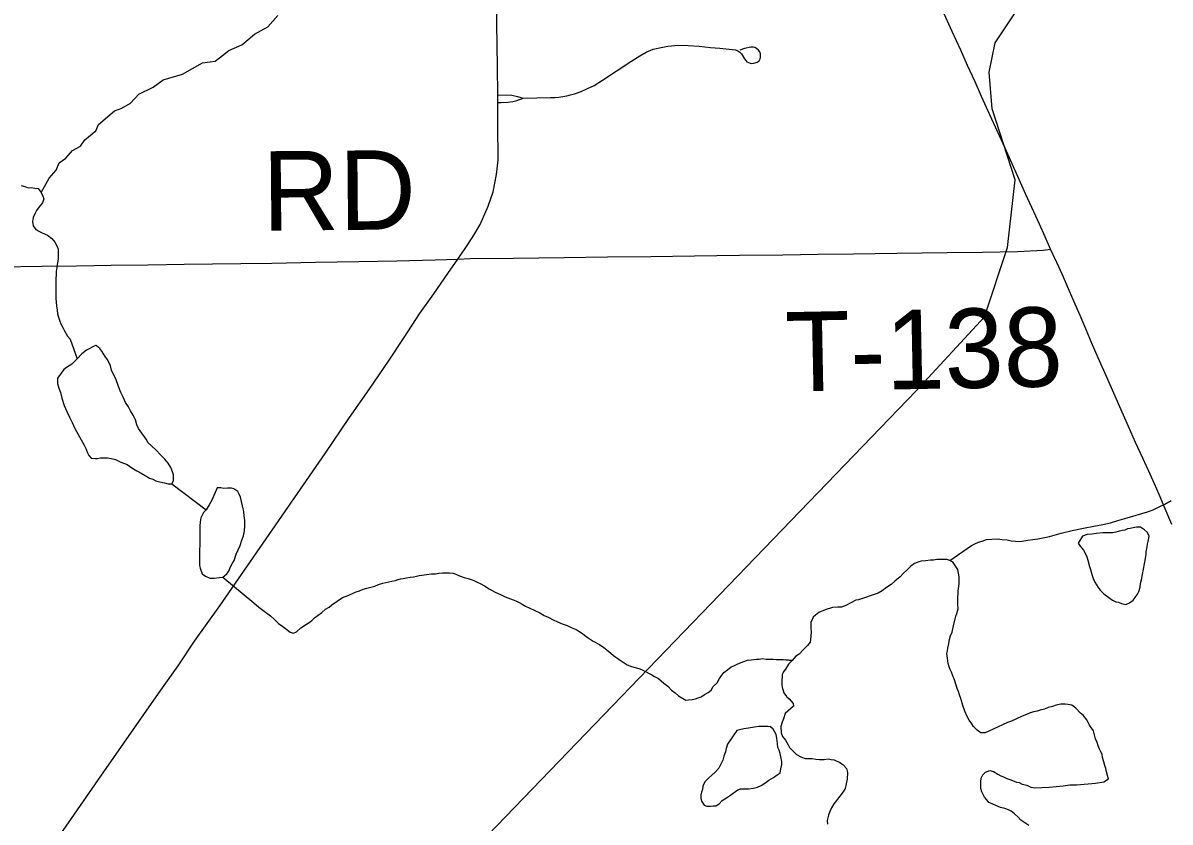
# Model space of a CAD drawing. Extents: x 103424 to 290657, y 38711 to 110967.
# Drawn here: x 167708 to 172070, y 45205 to 48243 of the extents above; entities that cross this region are included whole.
import ezdxf

# ---------------------------------------------------------------- set-up
doc = ezdxf.new("R2010")
doc.units = 0
for name, color, linetype in [('GM_X_County_Road', 7, 'Continuous'), ('GM_X_Minor_Lake', 7, 'Continuous'), ('GM_X_Minor_River', 7, 'Continuous'), ('GM_X_Rail_Line', 7, 'Continuous'), ('GM_X_State_Route', 7, 'Continuous'), ('GM_X_Township_Road', 7, 'Continuous'), ('GM_X_Township_Road_Text', 7, 'Continuous')]:
    doc.layers.add(name, color=color, linetype=linetype)

msp = doc.modelspace()

# ---------------------------------------------------------------- linework, layer by layer
at = {"layer": 'GM_X_County_Road'}
msp.add_lwpolyline([(167838.1, 45140.8), (167926.6, 45268.8), (168015.1, 45396.8), (168091.4, 45505.3), (168167.7, 45613.9), (168232.8, 45706.4), (168298, 45799), (168360.2, 45892.5), (168408.5, 45959.8), (168456.8, 46027.1), (168550.6, 46162.9), (168644.4, 46298.7), (168703.8, 46384.7), (168763.2, 46470.8), (168856.8, 46606.8), (168950.3, 46742.8), (169024, 46850), (169097.7, 46957.1), (169156.9, 47047), (169216.2, 47136.8), (169269.8, 47213.8), (169323.5, 47290.9), (169361.7, 47344.7), (169389, 47385.5), (169418.7, 47429.8), (169446.4, 47476.7), (169477.5, 47545.9), (169496.2, 47601), (169508.2, 47667.3), (169514.6, 47721.2), (169514, 47856.4), (169513.7, 47940), (169513.4, 47969.6), (169512.2, 48075.7), (169510.3, 48240.8), (169509.3, 48332)], dxfattribs=at)
at = {"layer": 'GM_X_Minor_Lake'}
for points in [[(167984, 47017.3), (167949.9, 46998.8), (167931.8, 46984.6), (167913.8, 46966.3), (167893.8, 46945.9), (167873.8, 46933.7), (167863.7, 46925.5), (167853.8, 46911.3), (167839.8, 46893.1), (167839.9, 46872.9), (167844.1, 46854.8), (167850.3, 46838.7), (167856.5, 46816.5), (167864.8, 46788.3), (167875.1, 46766.2), (167885.3, 46744.1), (167895.5, 46724), (167905.8, 46701.8), (167940.6, 46637.5), (167946.7, 46625.4), (167952.9, 46609.3), (167959, 46599.3), (167967.2, 46589.2), (167981.3, 46587.3), (167991.4, 46587.4), (168003.4, 46589.5), (168015.5, 46589.6), (168029.7, 46589.7), (168043.8, 46587.8), (168059.9, 46583.9), (168080.2, 46573.9), (168104.5, 46564), (168122.7, 46552), (168140.9, 46540.1), (168157.1, 46532.1), (168173.4, 46522.1), (168189.6, 46512.2), (168201.7, 46508.2), (168213.8, 46502.2)], [(167984, 47017.3), (167949.9, 46998.8), (167931.8, 46984.6), (167913.8, 46966.3), (167893.8, 46945.9), (167873.8, 46933.7), (167863.7, 46925.5), (167853.8, 46911.3), (167839.8, 46893.1), (167839.9, 46872.9), (167844.1, 46854.8), (167850.3, 46838.7), (167856.5, 46816.5), (167864.8, 46788.3), (167875.1, 46766.2), (167885.3, 46744.1), (167895.5, 46724), (167905.8, 46701.8), (167940.6, 46637.5), (167946.7, 46625.4), (167952.9, 46609.3), (167959, 46599.3), (167967.2, 46589.2), (167981.3, 46587.3), (167991.4, 46587.4), (168003.4, 46589.5), (168015.5, 46589.6), (168029.7, 46589.7), (168043.8, 46587.8), (168059.9, 46583.9), (168080.2, 46573.9), (168104.5, 46564), (168122.7, 46552), (168140.9, 46540.1), (168157.1, 46532.1), (168173.4, 46522.1), (168189.6, 46512.2), (168201.7, 46508.2), (168213.8, 46502.2), (168228, 46498.3), (168246.2, 46494.4), (168260.3, 46490.5), (168274.4, 46490.6), (168280.4, 46502.7), (168280.3, 46514.8), (168280.2, 46524.9), (168276.1, 46537), (168269.9, 46553.1), (168259.7, 46569.2), (168247.5, 46585.2), (168231.2, 46601.3), (168214.9, 46619.3), (168196.7, 46635.3), (168184.5, 46647.3), (168176.3, 46661.4), (168147.8, 46701.6), (168141.6, 46715.7), (168135.4, 46733.8), (168127.2, 46751.9), (168117, 46768), (168108.8, 46784), (168098.6, 46800.1), (168090.4, 46818.2), (168080.2, 46838.3), (168071.9, 46860.5), (168061.6, 46890.7), (168051.4, 46908.8), (168045.2, 46922.8), (168041.1, 46939), (168034.9, 46953), (168028.8, 46965.1), (168020.6, 46975.1), (168014.5, 46985.2), (168008.4, 46995.2), (168000.2, 47005.3), (167988.1, 47015.3), (167986, 47017.3), (167984, 47017.3)], [(168213.8, 46502.2), (168228, 46498.3), (168246.2, 46494.4), (168260.3, 46490.5), (168274.4, 46490.6), (168280.4, 46502.7), (168280.3, 46514.8), (168280.2, 46524.9), (168276.1, 46537), (168269.9, 46553.1), (168259.7, 46569.2), (168247.5, 46585.2), (168231.2, 46601.3), (168214.9, 46619.3), (168196.7, 46635.3), (168184.5, 46647.3), (168176.3, 46661.4), (168147.8, 46701.6), (168141.6, 46715.7), (168135.4, 46733.8), (168127.2, 46751.9), (168117, 46768), (168108.8, 46784), (168098.6, 46800.1), (168090.4, 46818.2), (168080.2, 46838.3), (168071.9, 46860.5), (168061.6, 46890.7), (168051.4, 46908.8), (168045.2, 46922.8), (168041.1, 46939), (168034.9, 46953), (168028.8, 46965.1), (168020.6, 46975.1), (168014.5, 46985.2), (168008.4, 46995.2), (168000.2, 47005.3), (167988.1, 47015.3), (167986, 47017.3), (167984, 47017.3)], [(168445.9, 46475.7), (168426.1, 46429.1), (168416.2, 46410.9), (168404.2, 46392.6), (168394.2, 46382.5), (168384.3, 46362.2), (168382.4, 46346), (168380.5, 46329.9), (168380.6, 46311.7), (168380.8, 46293.6), (168380.9, 46279.4), (168381, 46267.3), (168381.1, 46255.2), (168379.2, 46243.1), (168379.3, 46222.9), (168379.4, 46210.8), (168379.5, 46196.7), (168379.6, 46180.5), (168381.7, 46170.4), (168390, 46148.3), (168402.1, 46140.3), (168418.3, 46132.4), (168434.5, 46132.5), (168454.6, 46134.6), (168468.7, 46136.8), (168482.7, 46149), (168490.7, 46159.1), (168496.6, 46175.3), (168504.6, 46189.5), (168510.6, 46199.6), (168518.4, 46223.9), (168526.4, 46240.1), (168534.3, 46256.3), (168540.2, 46276.6), (168546.1, 46292.8), (168550, 46313), (168551.9, 46331.1), (168551.7, 46351.3), (168549.6, 46369.5), (168547.4, 46385.6), (168545.3, 46395.7), (168543.2, 46407.8), (168539.1, 46423.9), (168534.9, 46440), (168530.8, 46452.1), (168524.7, 46462.1), (168510.5, 46472.1), (168500.4, 46474.1), (168486.3, 46474), (168472.2, 46473.9), (168460, 46475.8), (168449.9, 46475.7), (168445.9, 46475.7)], [(168445.9, 46475.7), (168426.1, 46429.1), (168416.2, 46410.9), (168404.2, 46392.6), (168394.2, 46382.5), (168384.3, 46362.2), (168382.4, 46346), (168380.5, 46329.9), (168380.6, 46311.7), (168380.8, 46293.6), (168380.9, 46279.4), (168381, 46267.3), (168381.1, 46255.2), (168379.2, 46243.1), (168379.3, 46222.9), (168379.4, 46210.8), (168379.5, 46196.7), (168379.6, 46180.5), (168381.7, 46170.4), (168390, 46148.3), (168402.1, 46140.3), (168418.3, 46132.4), (168434.5, 46132.5), (168454.6, 46134.6), (168468.7, 46136.8), (168482.7, 46149), (168490.7, 46159.1)], [(168490.7, 46159.1), (168496.6, 46175.3), (168504.6, 46189.5), (168510.6, 46199.6), (168518.4, 46223.9), (168526.4, 46240.1), (168534.3, 46256.3), (168540.2, 46276.6), (168546.1, 46292.8), (168550, 46313), (168551.9, 46331.1), (168551.7, 46351.3), (168549.6, 46369.5), (168547.4, 46385.6), (168545.3, 46395.7), (168543.2, 46407.8), (168539.1, 46423.9), (168534.9, 46440), (168530.8, 46452.1), (168524.7, 46462.1), (168510.5, 46472.1), (168500.4, 46474.1), (168486.3, 46474), (168472.2, 46473.9), (168460, 46475.8), (168449.9, 46475.7), (168445.9, 46475.7)], [(171976.3, 46206.8), (171976.7, 46208.9), (171978.6, 46221), (171978.5, 46233.1), (171982.4, 46251.3), (171984.3, 46261.4), (171986.3, 46271.5), (171990.1, 46291.8), (171984, 46305.8), (171971.8, 46315.8), (171957.6, 46325.8), (171941.5, 46325.7), (171929.4, 46323.6), (171917.3, 46321.5), (171907.3, 46319.4), (171897.2, 46315.3), (171887.1, 46313.2), (171877.1, 46311.1), (171863, 46307), (171850.9, 46304.9), (171834.8, 46304.7), (171814.6, 46304.6), (171790.4, 46302.4), (171772.3, 46300.3), (171754.2, 46298.1), (171736.1, 46291.9), (171720.4, 46265.9)], [(171720.4, 46265.9), (171728.3, 46253.5), (171740.5, 46239.5), (171746.7, 46227.4), (171752.8, 46213.3), (171756.9, 46201.2), (171763.2, 46177.1), (171767.3, 46165), (171773.5, 46142.8), (171777.6, 46130.7), (171783.8, 46116.7), (171796.1, 46096.6), (171804.2, 46086.5), (171818.4, 46072.5), (171836.7, 46058.5), (171850.9, 46048.5), (171863, 46042.6), (171873.1, 46040.6), (171885.2, 46036.7), (171901.4, 46032.8), (171915.5, 46038.9), (171929.5, 46049.1), (171937.5, 46059.3), (171945.5, 46071.4), (171951.4, 46081.6), (171955.3, 46097.7), (171957.3, 46111.9), (171961.2, 46126), (171976.3, 46206.8)], [(171786.4, 45521.2), (171782.2, 45537.4), (171778.1, 45551.5), (171771.9, 45561.5), (171763.8, 45573.6), (171753.5, 45593.7), (171739.3, 45611.7), (171729.2, 45619.7), (171710.9, 45637.8), (171696.7, 45649.8), (171680.5, 45651.7), (171670.4, 45653.6), (171654.3, 45653.5), (171636.2, 45649.3), (171622.1, 45645.2), (171606, 45641), (171591.9, 45634.9), (171575.8, 45630.7), (171563.8, 45626.6), (171551.7, 45624.5), (171537.6, 45620.3), (171523.5, 45614.2), (171507.5, 45608), (171485.3, 45597.8), (171467.3, 45589.5), (171451.2, 45583.4), (171396.9, 45558.8), (171380.8, 45550.6), (171366.8, 45544.4), (171350.7, 45544.3), (171336.5, 45554.3), (171322.2, 45568.3), (171316.1, 45578.3), (171305.9, 45592.4), (171297.8, 45606.5), (171289.5, 45626.6), (171281.3, 45648.7), (171275.1, 45670.9), (171268.9, 45689), (171264.8, 45701.1), (171260.6, 45713.2), (171254.5, 45729.3), (171250.3, 45745.4), (171244.1, 45761.5), (171238, 45775.6), (171233.9, 45785.7), (171229.8, 45795.7), (171225.6, 45807.8), (171223.5, 45828), (171221.3, 45846.1), (171223.2, 45856.2), (171225.2, 45866.3), (171227.1, 45878.4), (171231, 45898.7), (171234.9, 45912.8), (171240.8, 45927), (171246.7, 45951.2), (171252.6, 45977.5), (171254.5, 45987.6), (171258.4, 45997.8), (171264.3, 46016), (171262.2, 46034.1), (171262.1, 46050.3), (171263.8, 46084.6), (171267.7, 46110.9), (171267.5, 46137.1), (171265.3, 46151.2), (171263.2, 46165.3), (171255, 46177.4), (171244.9, 46191.4), (171232.7, 46199.4), (171220.6, 46203.4), (171206.4, 46203.3), (171194.4, 46203.2), (171182.3, 46203.1), (171170.2, 46201), (171158.1, 46200.9), (171139.9, 46198.7), (171123.8, 46196.6), (171113.8, 46194.5), (171097.7, 46188.3), (171083.6, 46178.1), (171067.6, 46161.9), (171055.6, 46151.7), (171043.6, 46137.5), (171023.6, 46121.2), (171009.6, 46109), (170991.5, 46096.7), (170975.5, 46084.5), (170960.3, 46074.9)], [(170960.3, 46074.9), (170885, 46049.5), (170885, 46049.5), (170874.9, 46049.4), (170836.8, 46029), (170820.7, 46022.8), (170806.6, 46022.7), (170786.4, 46020.5), (170758.3, 46012.3), (170734.1, 46002), (170722.1, 45991.8), (170712.1, 45983.7), (170704.2, 45963.4), (170704.3, 45945.3), (170704.5, 45927.1), (170702.7, 45898.8), (170700.7, 45888.7), (170690.8, 45876.5), (170674.7, 45860.3), (170658.8, 45844), (170646.7, 45835.8), (170632.7, 45819.6), (170618.7, 45805.4), (170606.8, 45787.1), (170598.8, 45774.9), (170594.8, 45764.8), (170593, 45738.6), (170593.1, 45728.5), (170595.2, 45718.4), (170601.4, 45696.2), (170611.6, 45682.2), (170621.7, 45674.2), (170636, 45656.1), (170638.1, 45646), (170606, 45617.6), (170600.1, 45597.3), (170594.2, 45585.2), (170590.3, 45569), (170590.5, 45544.8), (170596.6, 45530.7), (170606.8, 45516.6), (170617, 45498.5), (170623.2, 45488.5), (170635.4, 45476.5), (170649.6, 45462.4), (170667.8, 45452.5), (170682, 45446.5), (170696.1, 45446.7), (170708.2, 45446.7), (170722.3, 45444.8), (170736.4, 45442.9), (170754.6, 45443), (170770.7, 45445.2), (170780.8, 45443.2), (170792.9, 45441.3), (170803, 45437.3), (170813.1, 45433.4), (170827.3, 45423.4), (170839.5, 45409.3), (170843.7, 45393.2), (170841.9, 45369), (170838, 45350.8), (170834.1, 45332.6), (170826.1, 45320.4), (170814.1, 45304.2), (170800.2, 45285.9), (170790.2, 45271.7), (170782.2, 45259.6), (170776.3, 45245.4), (170770.3, 45231.2), (170766.4, 45211), (170766.6, 45196.9)], [(170423, 45553.6), (170387.2, 45500.9), (170381.2, 45484.7), (170379.3, 45472.6), (170373.4, 45456.4), (170369.5, 45440.2), (170361.5, 45426), (170353.6, 45409.8), (170339.6, 45395.6), (170327.6, 45383.4), (170315.6, 45373.2), (170301.5, 45359), (170293.6, 45342.8), (170291.7, 45328.6), (170287.7, 45318.5), (170285.8, 45308.4), (170285.9, 45296.3), (170288, 45284.2), (170298.2, 45270.1), (170308.3, 45266.2), (170322.4, 45266.3), (170332.5, 45266.4), (170342.6, 45266.4), (170354.6, 45274.6), (170366.6, 45286.8), (170382.7, 45297), (170398.7, 45307.2), (170408.8, 45315.4), (170426.8, 45327.6), (170436.8, 45331.7), (170448.9, 45331.8), (170467.1, 45331.9), (170485.2, 45334.1), (170501.3, 45338.2), (170515.4, 45344.4), (170529.4, 45352.6), (170543.5, 45364.8), (170561.5, 45375), (170575.6, 45385.2), (170587.6, 45391.3), (170589.5, 45407.5), (170593.4, 45423.7), (170593.3, 45435.8), (170589.2, 45453.9), (170587, 45466), (170582.9, 45478.1), (170578.8, 45488.2), (170576.7, 45504.3), (170574.5, 45524.5), (170572.4, 45538.6), (170560.1, 45558.7), (170550, 45566.7), (170539.9, 45568.6), (170505.6, 45568.4), (170489.5, 45566.2), (170467.3, 45562), (170449.2, 45559.9), (170433.1, 45555.7), (170423, 45553.6)], [(170423, 45553.6), (170387.2, 45500.9), (170381.2, 45484.7), (170379.3, 45472.6), (170373.4, 45456.4), (170369.5, 45440.2), (170361.5, 45426), (170353.6, 45409.8), (170339.6, 45395.6), (170327.6, 45383.4), (170315.6, 45373.2), (170301.5, 45359), (170293.6, 45342.8), (170291.7, 45328.6), (170287.7, 45318.5), (170285.8, 45308.4), (170285.9, 45296.3), (170288, 45284.2), (170298.2, 45270.1), (170308.3, 45266.2), (170322.4, 45266.3), (170332.5, 45266.4), (170342.6, 45266.4), (170354.6, 45274.6), (170366.6, 45286.8), (170382.7, 45297), (170398.7, 45307.2), (170408.8, 45315.4), (170426.8, 45327.6), (170436.8, 45331.7)], [(170436.8, 45331.7), (170448.9, 45331.8), (170467.1, 45331.9), (170485.2, 45334.1), (170501.3, 45338.2), (170515.4, 45344.4), (170529.4, 45352.6), (170543.5, 45364.8), (170561.5, 45375), (170575.6, 45385.2), (170587.6, 45391.3), (170589.5, 45407.5), (170593.4, 45423.7), (170593.3, 45435.8), (170589.2, 45453.9), (170587, 45466), (170582.9, 45478.1), (170578.8, 45488.2), (170576.7, 45504.3), (170574.5, 45524.5), (170572.4, 45538.6), (170560.1, 45558.7), (170550, 45566.7), (170539.9, 45568.6), (170505.6, 45568.4), (170489.5, 45566.2), (170467.3, 45562), (170449.2, 45559.9), (170433.1, 45555.7), (170423, 45553.6)], [(171532.8, 45192.4), (171502.4, 45212.3), (171492.2, 45224.4), (171478, 45236.4), (171465.9, 45246.4), (171455.7, 45252.4), (171441.6, 45256.3), (171425.4, 45260.2), (171407.2, 45268.2), (171393.1, 45274.1), (171380.9, 45280.1), (171372.8, 45290.1), (171364.6, 45300.2), (171358.5, 45310.2), (171354.4, 45320.3), (171350.3, 45332.3), (171350.2, 45346.5), (171350.1, 45358.6), (171352, 45372.7), (171357.9, 45384.9), (171367.9, 45395), (171384, 45401.2), (171398.2, 45397.3), (171414.4, 45387.3), (171426.5, 45381.3), (171436.6, 45377.4), (171448.8, 45371.4), (171460.9, 45367.5), (171471, 45363.5), (171485.2, 45357.6), (171495.3, 45355.6), (171507.4, 45349.6), (171525.6, 45345.7), (171539.8, 45337.8), (171557.9, 45335.9), (171582.1, 45336.1), (171610.3, 45338.3), (171636.5, 45340.5), (171662.7, 45342.7), (171688.9, 45346.9), (171715.1, 45347.1), (171785.6, 45353.7), (171817.9, 45358), (171835.9, 45370.2), (171831.8, 45382.3), (171827.7, 45396.4), (171825.5, 45408.5), (171821.4, 45420.6), (171817.3, 45434.7), (171813.1, 45450.8), (171811, 45462.9), (171806.9, 45472.9), (171800.8, 45483), (171796.7, 45495.1), (171792.5, 45507.2), (171786.4, 45521.2)]]:
    msp.add_lwpolyline(points, dxfattribs=at)
at = {"layer": 'GM_X_Minor_River'}
for points in [[(167777.9, 47599), (167808.1, 47652.8), (167834.3, 47683.1), (167846.4, 47711.4), (167870.6, 47729.6), (167896.8, 47757.8), (167927, 47774), (167943.2, 47798.2), (167985.5, 47832.6), (167995.6, 47856.8), (168056.1, 47909.3), (168084.3, 47919.5), (168116.5, 47937.6), (168148.8, 47972), (168203.2, 47998.3), (168241.5, 48026.6), (168314.1, 48048.8), (168390.7, 48091.3), (168439.1, 48097.4), (168467.3, 48119.6), (168491.5, 48137.8), (168539.9, 48160.1), (168588.3, 48200.5), (168638.7, 48228.8), (168677, 48271.2)], [(167701, 47624.7), (167715.2, 47620.8), (167727.3, 47616.8), (167739.4, 47616.9), (167753.5, 47615), (167765.7, 47613.1), (167777.9, 47599), (167784, 47584.9), (167788.1, 47574.9), (167782.2, 47558.7), (167770.2, 47544.5), (167760.2, 47530.3), (167754.3, 47520.1), (167746.3, 47503.9), (167744.4, 47487.8), (167746.6, 47471.6), (167756.8, 47457.6), (167768.9, 47451.6), (167781.1, 47445.7), (167801.3, 47435.7), (167817.5, 47423.7), (167829.7, 47409.7), (167837.9, 47393.6), (167842, 47383.5), (167842.1, 47371.4), (167842.2, 47359.3), (167842.3, 47347.2), (167840.4, 47337.1), (167838.5, 47325), (167836.5, 47312.9), (167834.6, 47298.7), (167834.8, 47284.6), (167832.8, 47272.5), (167832.9, 47258.3), (167833, 47246.2), (167833.1, 47234.1), (167833.3, 47213.9), (167833.4, 47195.8), (167835.6, 47167.5), (167837.8, 47151.4), (167839.9, 47137.3), (167844.1, 47121.2), (167848.2, 47109.1), (167852.3, 47099), (167860.5, 47082.9), (167866.6, 47072.9), (167876.9, 47052.8), (167887, 47040.8), (167913.8, 46966.3)], [(168274.4, 46490.6), (168404.2, 46392.6)], [(171232.7, 46199.4), (171314.9, 46256.5), (171327, 46262.7), (171341, 46268.8), (171355.1, 46273), (171371.2, 46279.2), (171391.4, 46281.3), (171413.5, 46281.5), (171431.7, 46279.6), (171449.9, 46277.7), (171466, 46273.8), (171498.3, 46272), (171528.5, 46276.3), (171566.8, 46282.6), (171611.1, 46291), (171655.3, 46303.4), (171697.6, 46313.8), (171739.9, 46322.2), (171780.1, 46330.6), (171814.4, 46336.9), (171842.6, 46343.2), (171870.7, 46351.4), (171906.9, 46361.8), (171983.4, 46384.6), (172005.5, 46392.8), (172027.6, 46403), (172049.7, 46413.3), (172073.8, 46427.6)], [(168468.7, 46136.8), (168586.4, 46038.7), (168604.7, 46022.7), (168625, 46006.7), (168649.3, 45988.7), (168663.5, 45976.7), (168679.8, 45960.7), (168696, 45948.7), (168706.1, 45940.7), (168724.4, 45926.7), (168736.5, 45922.8), (168748.6, 45928.9), (168764.6, 45943.1), (168786.7, 45957.4), (168796.7, 45963.6), (168806.7, 45971.7), (168816.7, 45981.9), (168830.8, 45992.1), (168844.8, 46002.3), (168858.8, 46014.5), (168872.9, 46022.7), (168882.9, 46030.8), (168923, 46059.4), (168947.1, 46067.6), (168963.2, 46075.8), (168975.3, 46079.9), (168987.3, 46084.1), (169001.4, 46090.2), (169015.5, 46094.3), (169025.5, 46096.5), (169045.6, 46102.6), (169059.7, 46108.8), (169075.8, 46113), (169110, 46121.3), (169124.1, 46123.4), (169134.2, 46127.5), (169144.2, 46129.6), (169154.3, 46131.7), (169166.4, 46133.8), (169180.5, 46135.9), (169192.6, 46138), (169204.7, 46140.2), (169214.7, 46142.2), (169224.8, 46144.3), (169242.9, 46146.5), (169261.1, 46148.6), (169277.2, 46148.8), (169289.3, 46150.9), (169303.4, 46153), (169317.5, 46153.1), (169329.6, 46153.2), (169343.7, 46151.3), (169353.8, 46147.3), (169368, 46141.3), (169386.2, 46135.4), (169400.3, 46131.5), (169412.4, 46127.5), (169422.6, 46123.6), (169434.7, 46117.6), (169446.8, 46111.6), (169463, 46103.7), (169481.3, 46091.7), (169503.6, 46079.8), (169523.8, 46069.8), (169542, 46061.9), (169582.4, 46046), (169594.6, 46040.1), (169606.7, 46034.1), (169618.9, 46026.1), (169635.1, 46018.2), (169651.3, 46010.2), (169673.5, 46000.3), (169689.8, 45990.3), (169708, 45982.4), (169724.1, 45974.4), (169740.3, 45966.5), (169758.5, 45958.5), (169776.8, 45952.6), (169792.9, 45944.6), (169811.1, 45936.7), (169831.4, 45924.7), (169853.7, 45908.7), (169876, 45892.8), (169900.3, 45880.8), (169916.5, 45868.8), (169934.8, 45854.9), (169953, 45838.8), (169975.4, 45822.8), (169993.6, 45810.9), (170005.8, 45802.9), (170021.9, 45797), (170036.1, 45793), (170050.2, 45789.1), (170060.3, 45785.1), (170074.5, 45777.2), (170086.7, 45771.2), (170098.8, 45765.2), (170108.9, 45759.2), (170125.1, 45751.3), (170145.4, 45733.3)], [(170145.4, 45733.3), (170159.6, 45721.3), (170173.9, 45707.2), (170188, 45697.2), (170200.2, 45685.2), (170228.6, 45669.3), (170238.7, 45669.4), (170252.8, 45671.5), (170264.8, 45673.6), (170274.9, 45677.7), (170287, 45681.8), (170299, 45690), (170313, 45698.2), (170325.1, 45706.3), (170333, 45720.5), (170347, 45734.7), (170357, 45751), (170365, 45763.1), (170373, 45773.3), (170387, 45783.5), (170401, 45795.7), (170411.1, 45799.8), (170423.1, 45805.9), (170439.2, 45812.1), (170449.3, 45816.2), (170463.3, 45820.4), (170477.4, 45822.5), (170497.6, 45824.7), (170507.7, 45824.7), (170519.7, 45826.8), (170533.9, 45824.9), (170544, 45825), (170560.1, 45825.1), (170572.2, 45823.2), (170582.3, 45823.3), (170598.4, 45823.4), (170632.7, 45819.6), (170606.5, 45821.4)]]:
    msp.add_lwpolyline(points, dxfattribs=at)
at = {"layer": 'GM_X_Rail_Line'}
msp.add_lwpolyline([(146504.9, 45437.9), (151249.2, 45325.6), (154443.7, 45236.2), (154715.5, 45192.7), (154903.9, 45112.9), (155904.2, 44438.6), (156034.7, 44384.2), (156194.1, 44362.5), (156810.2, 44362.5), (161177.6, 44481.6), (161906.5, 44481.2), (168026.1, 44546.6), (168178.1, 44543.3), (168898.2, 44555.7), (171103.9, 46845), (171363.9, 47125.7), (171451.7, 47389.1), (171481, 47646.7), (171393.2, 47915.9), (171381.5, 48056.4), (171404.9, 48167.6), (171498.5, 48308.1), (174523.8, 51299.4), (175679.7, 52376.9)], dxfattribs=at)
at = {"layer": 'GM_X_State_Route'}
msp.add_lwpolyline([(172076, 46336.3), (172051, 46395.6), (172027.7, 46450.8), (172009.9, 46490.7), (171993.5, 46527.2), (171965.9, 46588.1), (171938.7, 46648.2), (171911.4, 46708.4), (171878.7, 46783.6), (171855.7, 46835.8), (171827.8, 46899.2), (171796.4, 46970.5), (171770.8, 47028.9), (171745.5, 47089.3), (171727.4, 47130.8), (171703.6, 47185.6), (171679.4, 47241.3), (171660.4, 47284.9), (171639.6, 47332.7), (171625.4, 47361.6), (171615.6, 47383.2), (171594.5, 47429.9), (171572.8, 47477.9), (171551.4, 47525.3), (171521.5, 47591.5), (171496, 47647.8), (171463.8, 47719), (171442.1, 47767.2), (171413.5, 47830.4), (171384.7, 47894), (171353.2, 47963.9), (171328.3, 48019), (171299.9, 48081.8), (171273.8, 48139.5), (171241.5, 48210.9), (171204.8, 48292.2)], dxfattribs=at)
at = {"layer": 'GM_X_Township_Road'}
for points in [[(169513.7, 47940), (169525.9, 47940.5), (169552.2, 47941.5), (169570.4, 47944.9), (169586.5, 47948.8), (169609.5, 47957.1), (169714.5, 47959.5), (169729.9, 47960.1), (169745.2, 47961.5), (169760.6, 47963.6), (169775.7, 47966.4), (169790.5, 47969.9), (169805.4, 47974.1), (169830.8, 47983), (169855.2, 47994), (169880.1, 48005.8), (169911.8, 48025), (170019.5, 48096.9), (170053.1, 48118.6), (170078.2, 48132.3), (170104.3, 48143), (170135, 48150.3), (170159.6, 48154.3), (170201, 48158.3), (170237.7, 48157.5), (170279.6, 48154.3), (170322.5, 48150.2), (170357.9, 48146.7), (170404.6, 48142.3), (170416.7, 48140.3), (170426.7, 48136.9), (170433.5, 48132.4), (170440, 48125.6), (170451.4, 48106.9), (170456, 48100.8), (170460.6, 48095.8), (170466.6, 48092.8), (170472.7, 48090.2), (170479.6, 48088.8), (170492.6, 48090.8), (170499.1, 48093.8), (170503.6, 48096.9), (170506.8, 48099.5), (170510.6, 48106.1), (170512.6, 48111.8), (170512.3, 48125.6), (170509.5, 48133), (170504.6, 48140.1), (170497.6, 48146.4), (170491.3, 48149.4), (170484.1, 48150.4), (170475.6, 48151.2), (170452, 48146.3), (170433.4, 48138.9)], [(169513.4, 47969.6), (169567.3, 47968.5), (169588.1, 47963.1), (169609.5, 47957.1)], [(167616.2, 47315.6), (167781.2, 47318.1), (167912.3, 47320.1), (168043.3, 47322.1), (168182.3, 47324.1), (168321.2, 47326.2), (168429, 47327.5), (168536.8, 47328.8), (168654.9, 47330), (168820, 47333.2), (168985, 47336.5), (169130, 47339.3), (169275, 47342.2), (169361.7, 47344.7), (169408.6, 47347.4), (169573.6, 47349.2), (169669.6, 47350.3), (169765.6, 47351.3), (169930.6, 47353.5), (170095.7, 47355.8), (170260.8, 47358), (170346.8, 47359.2), (170432.8, 47360.3), (170597.9, 47362.1), (170731.9, 47363.6), (170865.9, 47365.1), (171031, 47367.4), (171126.6, 47368.7), (171222.2, 47370.1), (171355.9, 47372.3), (171489.6, 47374.6), (171587.2, 47378.8), (171615.6, 47383.2)]]:
    msp.add_lwpolyline(points, dxfattribs=at)

# ---------------------------------------------------------------- texts
at = {"layer": 'GM_X_Township_Road_Text'}
for s, rotation, p in [('RD', 0.4838, (168619.7, 47453.3)), ('T-138', 1.1229, (170609.4, 46841.6))]:
    msp.add_text(s, height=301.87, rotation=rotation, dxfattribs=at).set_placement(p)

doc.saveas('drawing.dxf')
